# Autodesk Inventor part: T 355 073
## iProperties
Company: Mayer & Müller AG Schaltgeräte
Created: 2005-12
Part Number: T 355 073
Material: 2.0402.30
Document SubType Name: Modeling
Designer: I.Baliuc
Manufacturer: Standard
Standards Organization: Custom
Description: Bolzen
Density: 8.2 g/cm^3
HalbzeugNorm: DIN 1756
Zweck: Strombahn HN/HE 2000-4000
Abmessung: Rd 10 - 106
Author: T.Messerschmitt
Keywords: 267031
Revision Number: 355073
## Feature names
1. Extrusion2
2. Extrusion6
3. Extrusion7
4. Spiegeln2 [Mirror]
